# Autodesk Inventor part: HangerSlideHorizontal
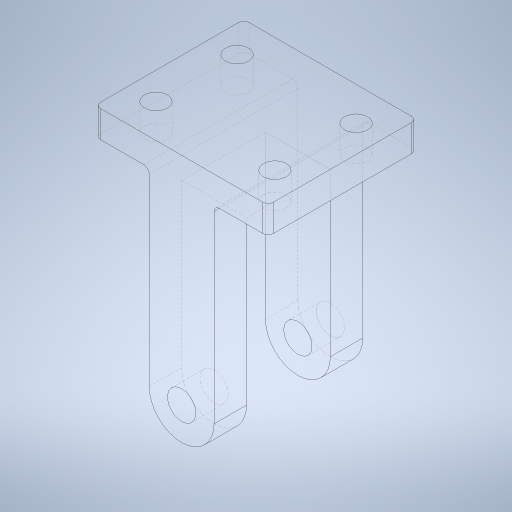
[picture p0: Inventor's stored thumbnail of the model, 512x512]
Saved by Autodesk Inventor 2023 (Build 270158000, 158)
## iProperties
Created: 2023-11
Part Number: HangerSlideHorizontal
Material: Generic
Document SubType Name: Modeling
Designer: tornqvih
Density: 1 g/cm^3
Appearance: Default
Mass: 84.659 g
Surface Area: 226.119 cm^2
Volume: 84.659 cm^3
Author: tornqvih
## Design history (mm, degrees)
sketch "Sketch1"
  geometry: L1 (-32, 0)-(-32, 10); L2 (-32, 10)-(32, 10); L3 (32, 10)-(32, 0); L4 (-32, 0)-(-12, 0); L5 (32, 0)-(12, 0); L6 (-44.8, 0)-(44.8, 0) reference; L7 (-12, 0)-(-12, -70); L8 (12, 0)-(12, -70); L9 (0, -100.4)-(0, 28.4) reference; A1 r 12 centre (0, -70) between (-12, -70) and (12, -70); 1 further point
  constraints: 14 end point, 3 point on line, 3 vertical, 2 horizontal, 2 perpendicular, 2 point on circle, 2 tangent, 1 centre point
  dimensions: "d0" = 10 distance of L1.start L1.end; "d3" = 20 distance of L1.start L4.end; "d4" = 20 distance of L3.end L5.end; "d7" = 12 radius of A1; "d8" = 70 distance of L4.end L7.end
extrude "Extrusion1" new body sketch "Sketch1" distance "d5" = 55; taper "d6" = 0 deg
sketch "Sketch2"
  geometry: L1 (0, -100.4)-(0, 28.4) reference; 3 further points
  constraints: 1 horizontal alignment, 1 point on line
hole "Hole1" sketch "Sketch2" at (0, -70) diameter "d9" = 10.5; stored, may be unused: countersink angle "d13" = 90 deg, drill point angle "d15" = 118 deg; dims "d10" = 6, "d11" = 4, "d12" = 2, "d14" = 8
sketch "Sketch3"
  geometry: L1 (0, 0)-(0, -55) reference; L2 (64, 0)-(0, 0) reference; L3 (64, -55)-(0, -55) reference; L4 (64, 0)-(64, -55) reference; 5 further points
  constraints: 3 horizontal alignment, 2 vertical alignment
  dimensions: "d16" = 10 distance from line of L1 point (10, -12.5); "d19" = 10 distance from line of L4 point (54, -12.5); "d28" = 30 distance of point (10, -42.5) point (10, -12.5); "d29" = 12.5 distance from line of L2 point (10, -12.5)
hole "Hole2" sketch "Sketch3" at (10, -12.5), (10, -42.5), (54, -12.5), (54, -42.5) diameter "d20" = 8.5; stored, may be unused: countersink angle "d24" = 90 deg, drill point angle "d26" = 118 deg; dims "d21" = 6, "d22" = 4, "d23" = 2, "d25" = 8
fillet "Fillet1" dims "d27" = 2
fillet "Fillet2" dims "d30" = 2
sketch "Sketch4"
  geometry: L1 (-10, 43)-(-90, 43); L2 (-90, 43)-(-90, 12); L3 (-90, 12)-(-10, 12); L4 (-10, 12)-(-10, 43); L5 (-2, 55)-(-2, 0) reference; L6 (-70, 55)-(-2, 55) reference; L7 (-70, 0)-(-2, 0) reference; 1 further point
  constraints: 8 end point, 2 parallel, 1 horizontal, 1 perpendicular
  dimensions: "d32" = 80 distance of L1.start L1.end; "d33" = 8 distance between parallel lines of L5 L4; "d34" = 12 distance between parallel lines of L6 L1; "d35" = 12 distance between parallel lines of L7 L3
extrude "Extrusion2" cut sketch "Sketch4" stored distance "d36" = 60; taper "d37" = 0 deg
body "Solid1"
